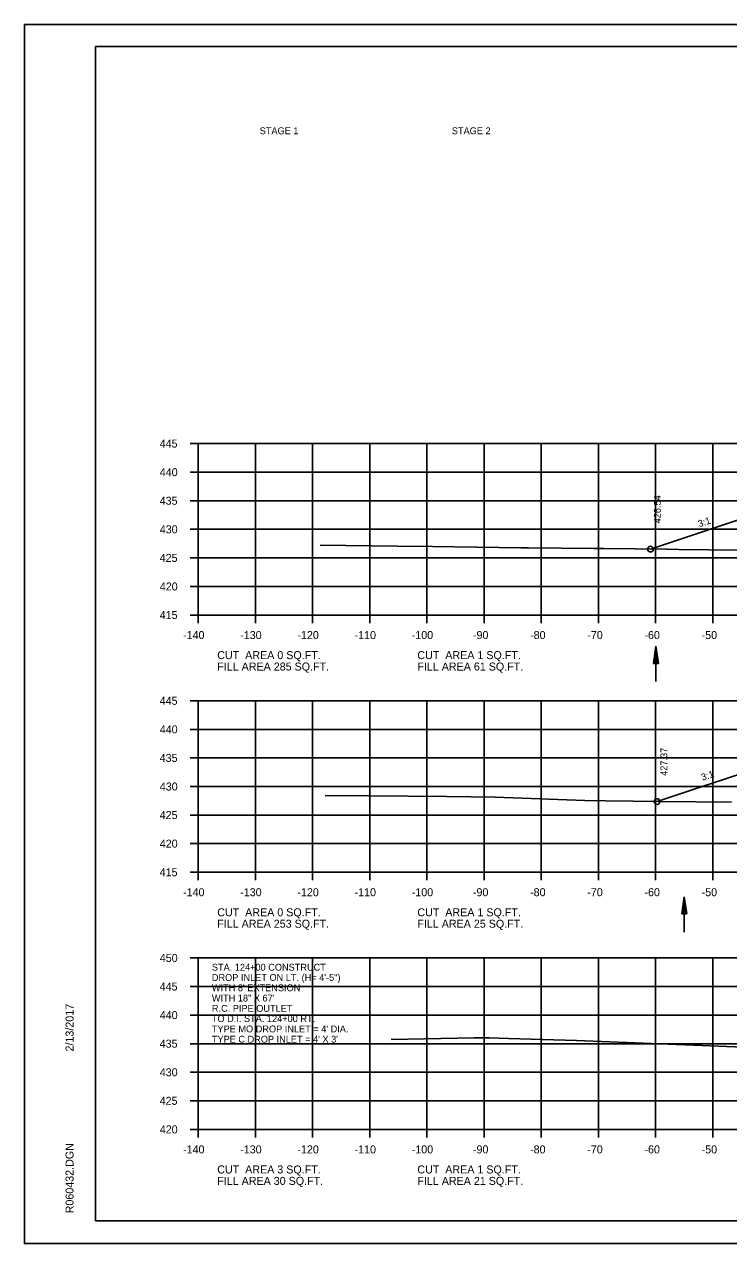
# Model space of a CAD drawing. Extents: x 1538688 to 1540766, y 656250 to 671912.
# Drawn here: x 1538687.8 to 1538810.9, y 659751.3 to 659964.6 of the extents above; entities that cross this region are included whole.
import ezdxf

# ---------------------------------------------------------------- set-up
doc = ezdxf.new("R2010")
doc.units = 0
for name, color, linetype in [('15', 7, 'Continuous'), ('18', 7, 'Continuous'), ('20', 7, 'Continuous'), ('22', 7, 'Continuous'), ('26', 7, 'Continuous'), ('39', 7, 'Continuous'), ('40', 7, 'Continuous'), ('41', 7, 'Continuous'), ('42', 7, 'Continuous'), ('Borings', 7, 'Continuous'), ('Default', 7, 'Continuous'), ('Horizontal Alignment', 7, 'Continuous'), ('RipRap', 7, 'Continuous')]:
    doc.layers.add(name, color=color, linetype=linetype)

msp = doc.modelspace()

# ---------------------------------------------------------------- linework, layer by layer
at = {"layer": '15'}
for p, q in [((1538797.79, 659852.84), (1538798.24, 659855.84)), ((1538797.86, 659852.84), (1538798.24, 659855.34)), ((1538798.69, 659852.84), (1538798.24, 659855.84)), ((1538798.61, 659852.84), (1538798.24, 659855.34)), ((1538797.94, 659852.84), (1538798.24, 659854.83)), ((1538798.01, 659852.84), (1538798.24, 659854.33)), ((1538798.09, 659852.84), (1538798.24, 659853.82)), ((1538798.16, 659852.84), (1538798.24, 659853.32)), ((1538798.53, 659852.84), (1538798.24, 659854.83)), ((1538798.46, 659852.84), (1538798.24, 659854.33)), ((1538798.38, 659852.84), (1538798.24, 659853.82)), ((1538798.31, 659852.84), (1538798.24, 659853.32)), ((1538797.79, 659852.84), (1538798.69, 659852.84)), ((1538802.73, 659808.99), (1538803.18, 659811.99)), ((1538802.8, 659808.99), (1538803.18, 659811.49)), ((1538802.88, 659808.99), (1538803.18, 659810.98)), ((1538803.63, 659808.99), (1538803.18, 659811.99)), ((1538803.55, 659808.99), (1538803.18, 659811.49)), ((1538803.48, 659808.99), (1538803.18, 659810.98)), ((1538802.73, 659808.99), (1538803.63, 659808.99)), ((1538802.96, 659808.99), (1538803.18, 659810.48)), ((1538803.03, 659808.99), (1538803.18, 659809.97)), ((1538803.11, 659808.99), (1538803.18, 659809.47)), ((1538803.4, 659808.99), (1538803.18, 659810.48)), ((1538803.33, 659808.99), (1538803.18, 659809.97)), ((1538803.25, 659808.99), (1538803.18, 659809.47))]:
    msp.add_line(p, q, dxfattribs=at)
at = {"layer": '18'}
for points in [[(1538739.49, 659873.53), (1538752.99, 659873.35), (1538759.16, 659873.28), (1538774.66, 659873.08), (1538775.94, 659873.06), (1538787.36, 659872.94), (1538789.1, 659872.91), (1538800.06, 659872.8), (1538802.22, 659872.77), (1538812.77, 659872.66)], [(1538740.37, 659829.72), (1538748.01, 659829.66), (1538754.89, 659829.61), (1538761.66, 659829.56), (1538770.1, 659829.41), (1538785.77, 659828.82), (1538789.43, 659828.8), (1538799.06, 659828.65), (1538811.44, 659828.53)], [(1538751.93, 659787.05), (1538766.41, 659787.29), (1538767.72, 659787.32), (1538769.05, 659787.29), (1538772.46, 659787.17), (1538784.35, 659786.82), (1538820.81, 659785.38)]]:
    msp.add_lwpolyline(points, dxfattribs=at)
at = {"layer": '20'}
for points in [[(1538797.27, 659872.83), (1538816.67, 659879.29), (1538821.67, 659879.19), (1538824.67, 659879.13), (1538825.17, 659879.13), (1538825.18, 659878.63), (1538826.18, 659878.65), (1538858.18, 659878.31), (1538890.18, 659877.67), (1538891.18, 659877.65), (1538891.19, 659878.15), (1538891.69, 659878.15), (1538894.69, 659878.21), (1538899.69, 659878.31), (1538916.84, 659872.59)], [(1538798.42, 659828.66), (1538816.67, 659834.74), (1538821.67, 659834.64), (1538824.67, 659834.58), (1538825.17, 659834.58), (1538825.18, 659834.08), (1538826.18, 659834.1), (1538858.18, 659833.85), (1538890.18, 659833.21), (1538891.18, 659833.19), (1538891.19, 659833.69), (1538891.69, 659833.69), (1538894.69, 659833.75), (1538899.69, 659833.85), (1538907.07, 659831.39)]]:
    msp.add_lwpolyline(points, dxfattribs=at)
at = {"layer": '22'}
for p, q in [((1538718.18, 659891.29), (1538998.18, 659891.29)), ((1538718.18, 659861.29), (1538718.18, 659891.29)), ((1538728.18, 659861.29), (1538728.18, 659891.29)), ((1538738.18, 659861.29), (1538738.18, 659891.29)), ((1538748.18, 659861.29), (1538748.18, 659891.29)), ((1538758.18, 659861.29), (1538758.18, 659891.29)), ((1538768.18, 659861.29), (1538768.18, 659891.29)), ((1538778.18, 659861.29), (1538778.18, 659891.29)), ((1538788.18, 659861.29), (1538788.18, 659891.29)), ((1538798.18, 659861.29), (1538798.18, 659891.29)), ((1538808.18, 659861.29), (1538808.18, 659891.29)), ((1538718.18, 659886.29), (1538998.18, 659886.29)), ((1538718.18, 659881.29), (1538998.18, 659881.29)), ((1538718.18, 659876.29), (1538998.18, 659876.29)), ((1538718.18, 659871.29), (1538998.18, 659871.29)), ((1538718.18, 659866.29), (1538998.18, 659866.29)), ((1538718.18, 659861.29), (1538998.18, 659861.29)), ((1538718.18, 659846.29), (1538998.18, 659846.29)), ((1538718.18, 659816.29), (1538718.18, 659846.29)), ((1538728.18, 659816.29), (1538728.18, 659846.29)), ((1538738.18, 659816.29), (1538738.18, 659846.29)), ((1538748.18, 659816.29), (1538748.18, 659846.29)), ((1538758.18, 659816.29), (1538758.18, 659846.29)), ((1538768.18, 659816.29), (1538768.18, 659846.29)), ((1538778.18, 659816.29), (1538778.18, 659846.29)), ((1538788.18, 659816.29), (1538788.18, 659846.29)), ((1538798.18, 659816.29), (1538798.18, 659846.29)), ((1538808.18, 659816.29), (1538808.18, 659846.29)), ((1538718.18, 659841.29), (1538998.18, 659841.29)), ((1538718.18, 659836.29), (1538998.18, 659836.29)), ((1538718.18, 659831.29), (1538998.18, 659831.29)), ((1538718.18, 659826.29), (1538998.18, 659826.29)), ((1538718.18, 659821.29), (1538998.18, 659821.29)), ((1538718.18, 659816.29), (1538998.18, 659816.29)), ((1538718.18, 659801.29), (1538998.18, 659801.29)), ((1538718.18, 659771.29), (1538718.18, 659801.29)), ((1538728.18, 659771.29), (1538728.18, 659801.29)), ((1538738.18, 659771.29), (1538738.18, 659801.29)), ((1538748.18, 659771.29), (1538748.18, 659801.29)), ((1538758.18, 659771.29), (1538758.18, 659801.29)), ((1538768.18, 659771.29), (1538768.18, 659801.29)), ((1538778.18, 659771.29), (1538778.18, 659801.29)), ((1538788.18, 659771.29), (1538788.18, 659801.29)), ((1538798.18, 659771.29), (1538798.18, 659801.29)), ((1538808.18, 659771.29), (1538808.18, 659801.29)), ((1538718.18, 659796.29), (1538998.18, 659796.29)), ((1538718.18, 659791.29), (1538998.18, 659791.29)), ((1538718.18, 659786.29), (1538998.18, 659786.29)), ((1538718.18, 659781.29), (1538998.18, 659781.29)), ((1538718.18, 659776.29), (1538998.18, 659776.29)), ((1538718.18, 659771.29), (1538998.18, 659771.29))]:
    msp.add_line(p, q, dxfattribs=at)
at = {"layer": '26'}
for p, q in [((1538687.78, 659964.64), (1539021.11, 659964.64)), ((1538687.78, 659751.31), (1539021.11, 659751.31))]:
    msp.add_line(p, q, dxfattribs=at)
msp.add_lwpolyline([(1538687.77, 659964.64), (1539021.11, 659964.64), (1539021.11, 659751.31), (1538687.77, 659751.31)], close=True, dxfattribs=at)
for centre in [(1538797.27, 659872.83), (1538798.42, 659828.66)]:
    msp.add_circle(centre, 0.5, dxfattribs=at)
at = {"layer": '39'}
for p, q in [((1538798.24, 659849.66), (1538798.24, 659855.84)), ((1538803.18, 659805.81), (1538803.18, 659811.99))]:
    msp.add_line(p, q, dxfattribs=at)
at = {"layer": 'Borings'}
for p, q in [((1538716.78, 659891.29), (1538718.18, 659891.29)), ((1538718.18, 659861.29), (1538718.18, 659891.29)), ((1538716.78, 659886.29), (1538718.18, 659886.29)), ((1538716.78, 659881.29), (1538718.18, 659881.29)), ((1538716.78, 659876.29), (1538718.18, 659876.29)), ((1538716.78, 659871.29), (1538718.18, 659871.29)), ((1538716.78, 659866.29), (1538718.18, 659866.29)), ((1538716.78, 659861.29), (1538718.18, 659861.29)), ((1538718.18, 659861.29), (1538998.18, 659861.29)), ((1538718.18, 659859.89), (1538718.18, 659861.29)), ((1538728.18, 659859.89), (1538728.18, 659861.29)), ((1538738.18, 659859.89), (1538738.18, 659861.29)), ((1538748.18, 659859.89), (1538748.18, 659861.29)), ((1538758.18, 659859.89), (1538758.18, 659861.29)), ((1538768.18, 659859.89), (1538768.18, 659861.29)), ((1538778.18, 659859.89), (1538778.18, 659861.29)), ((1538788.18, 659859.89), (1538788.18, 659861.29)), ((1538798.18, 659859.89), (1538798.18, 659861.29)), ((1538808.18, 659859.89), (1538808.18, 659861.29)), ((1538716.78, 659846.29), (1538718.18, 659846.29)), ((1538718.18, 659816.29), (1538718.18, 659846.29)), ((1538716.78, 659841.29), (1538718.18, 659841.29)), ((1538716.78, 659836.29), (1538718.18, 659836.29)), ((1538716.78, 659831.29), (1538718.18, 659831.29)), ((1538716.78, 659826.29), (1538718.18, 659826.29)), ((1538716.78, 659821.29), (1538718.18, 659821.29)), ((1538716.78, 659816.29), (1538718.18, 659816.29)), ((1538718.18, 659816.29), (1538998.18, 659816.29)), ((1538718.18, 659814.89), (1538718.18, 659816.29)), ((1538728.18, 659814.89), (1538728.18, 659816.29)), ((1538738.18, 659814.89), (1538738.18, 659816.29)), ((1538748.18, 659814.89), (1538748.18, 659816.29)), ((1538758.18, 659814.89), (1538758.18, 659816.29)), ((1538768.18, 659814.89), (1538768.18, 659816.29)), ((1538778.18, 659814.89), (1538778.18, 659816.29)), ((1538788.18, 659814.89), (1538788.18, 659816.29)), ((1538798.18, 659814.89), (1538798.18, 659816.29)), ((1538808.18, 659814.89), (1538808.18, 659816.29)), ((1538716.78, 659801.29), (1538718.18, 659801.29)), ((1538718.18, 659771.29), (1538718.18, 659801.29)), ((1538716.78, 659796.29), (1538718.18, 659796.29)), ((1538716.78, 659791.29), (1538718.18, 659791.29)), ((1538716.78, 659786.29), (1538718.18, 659786.29)), ((1538716.78, 659781.29), (1538718.18, 659781.29)), ((1538716.78, 659776.29), (1538718.18, 659776.29)), ((1538716.78, 659771.29), (1538718.18, 659771.29)), ((1538718.18, 659771.29), (1538998.18, 659771.29)), ((1538718.18, 659769.89), (1538718.18, 659771.29)), ((1538728.18, 659769.89), (1538728.18, 659771.29)), ((1538738.18, 659769.89), (1538738.18, 659771.29)), ((1538748.18, 659769.89), (1538748.18, 659771.29)), ((1538758.18, 659769.89), (1538758.18, 659771.29)), ((1538768.18, 659769.89), (1538768.18, 659771.29)), ((1538778.18, 659769.89), (1538778.18, 659771.29)), ((1538788.18, 659769.89), (1538788.18, 659771.29)), ((1538798.18, 659769.89), (1538798.18, 659771.29)), ((1538808.18, 659769.89), (1538808.18, 659771.29))]:
    msp.add_line(p, q, dxfattribs=at)
at = {"layer": 'RipRap'}
for p, q in [((1538700.18, 659960.75), (1539016.36, 659960.75)), ((1538700.18, 659755.29), (1538700.18, 659960.75)), ((1538700.18, 659755.29), (1538700.18, 659755.29)), ((1539016.36, 659755.29), (1538700.18, 659755.29))]:
    msp.add_line(p, q, dxfattribs=at)

# ---------------------------------------------------------------- texts
at = {"layer": '40'}
for s, p in [('STA. 124+00 CONSTRUCT', (1538720.56, 659799.07)), ('DROP INLET ON LT. (H= 4\'-5") ', (1538720.56, 659797.27)), ("WITH 8' EXTENSION ", (1538720.56, 659795.47)), ('WITH 18" X 67\'', (1538720.56, 659793.67)), ('R.C. PIPE OUTLET', (1538720.56, 659791.87)), ('TO D.I. STA. 124+00 RT.', (1538720.56, 659790.07)), ("TYPE MO DROP INLET = 4' DIA.", (1538720.56, 659788.27)), ("TYPE C DROP INLET = 4' X 3'", (1538720.56, 659786.47))]:
    msp.add_text(s, height=1.2, dxfattribs=at).set_placement(p)
at = {"layer": '41'}
for s, p in [('426.54', (1538799.07, 659877.33)), ('427.37', (1538800.22, 659833.16))]:
    msp.add_text(s, height=1.2, rotation=90, dxfattribs=at).set_placement(p)
at = {"layer": '42'}
for p in [(1538805.81, 659876.64), (1538806.38, 659832.28)]:
    msp.add_text('3:1', height=1.2, rotation=18.4349, dxfattribs=at).set_placement(p)
at = {"layer": 'Default'}
for s, p in [('STAGE 1', (1538728.93, 659945.42)), ('STAGE 2', (1538762.53, 659945.42))]:
    msp.add_text(s, height=1.2, dxfattribs=at).set_placement(p)
at = {"layer": 'Horizontal Alignment'}
for s, p in [('445', (1538711.43, 659890.59)), ('440', (1538711.45, 659885.59)), ('435', (1538711.43, 659880.59)), ('430', (1538711.45, 659875.59)), ('425', (1538711.43, 659870.59)), ('420', (1538711.45, 659865.59)), ('415', (1538711.43, 659860.59)), ('-140', (1538715.52, 659857.09)), ('-130', (1538725.52, 659857.09)), ('-120', (1538735.52, 659857.09)), ('-110', (1538745.52, 659857.09)), ('-100', (1538755.52, 659857.09)), ('-90', (1538766.22, 659857.09)), ('-80', (1538776.22, 659857.09)), ('-70', (1538786.22, 659857.09)), ('-60', (1538796.22, 659857.09)), ('-50', (1538806.22, 659857.09)), ('CUT  AREA 0 SQ.FT.', (1538721.5, 659853.58)), ('CUT  AREA 1 SQ.FT.', (1538756.5, 659853.58)), ('FILL AREA 285 SQ.FT.', (1538721.5, 659851.58)), ('FILL AREA 285 SQ.FT.', (1538721.5, 659851.58)), ('FILL AREA 61 SQ.FT.', (1538756.5, 659851.58)), ('445', (1538711.43, 659845.59)), ('440', (1538711.45, 659840.59)), ('435', (1538711.43, 659835.59)), ('430', (1538711.45, 659830.59)), ('425', (1538711.43, 659825.59)), ('420', (1538711.45, 659820.59)), ('415', (1538711.43, 659815.59)), ('-140', (1538715.52, 659812.09)), ('-130', (1538725.52, 659812.09)), ('-120', (1538735.52, 659812.09)), ('-110', (1538745.52, 659812.09)), ('-100', (1538755.52, 659812.09)), ('-90', (1538766.22, 659812.09)), ('-80', (1538776.22, 659812.09)), ('-70', (1538786.22, 659812.09)), ('-60', (1538796.22, 659812.09)), ('-50', (1538806.22, 659812.09)), ('CUT  AREA 0 SQ.FT.', (1538721.5, 659808.58)), ('CUT  AREA 1 SQ.FT.', (1538756.5, 659808.58)), ('FILL AREA 253 SQ.FT.', (1538721.5, 659806.58)), ('FILL AREA 25 SQ.FT.', (1538756.5, 659806.58)), ('450', (1538711.45, 659800.59)), ('445', (1538711.43, 659795.59)), ('440', (1538711.45, 659790.59)), ('435', (1538711.43, 659785.59)), ('430', (1538711.45, 659780.59)), ('425', (1538711.43, 659775.59)), ('420', (1538711.45, 659770.59)), ('-140', (1538715.52, 659767.09)), ('-130', (1538725.52, 659767.09)), ('-120', (1538735.52, 659767.09)), ('-110', (1538745.52, 659767.09)), ('-100', (1538755.52, 659767.09)), ('-90', (1538766.22, 659767.09)), ('-80', (1538776.22, 659767.09)), ('-70', (1538786.22, 659767.09)), ('-60', (1538796.22, 659767.09)), ('-50', (1538806.22, 659767.09)), ('CUT  AREA 3 SQ.FT.', (1538721.5, 659763.58)), ('CUT  AREA 1 SQ.FT.', (1538756.5, 659763.58)), ('FILL AREA 30 SQ.FT.', (1538721.5, 659761.58)), ('FILL AREA 21 SQ.FT.', (1538756.5, 659761.58))]:
    msp.add_text(s, height=1.4, dxfattribs=at).set_placement(p)
at = {"layer": 'RipRap'}
for s, p in [('2/13/2017', (1538696.37, 659784.93)), ('R060432.DGN', (1538696.37, 659756.61))]:
    msp.add_text(s, height=1.4, rotation=90, dxfattribs=at).set_placement(p)

doc.saveas('drawing.dxf')
